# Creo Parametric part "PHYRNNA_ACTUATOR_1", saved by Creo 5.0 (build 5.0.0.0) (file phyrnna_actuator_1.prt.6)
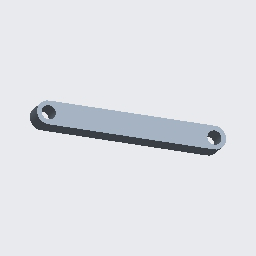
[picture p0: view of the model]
Units: Inch lbm Second (Pro/E Default); INCH, POUND, SECS

Created from: INLBS_PART_SOLID.PRT

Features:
  1. datum plane "RIGHT"
  2. datum plane "TOP"
  3. datum plane "FRONT"
  4. coordinate system
  5. sketch "REFERENCE"
  6. extrusion "Extrude 1"

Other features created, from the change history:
  sketch "Sketch 1"
  extrusion "Extrude 1"
  group "COPIED_GROUP" (2 times)
  sketch "REFERENCE" (2 times)

Other named items: ACTUATOR_S, ACTUATOR_E

Surfaces: 4 plane, 4 cylinder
